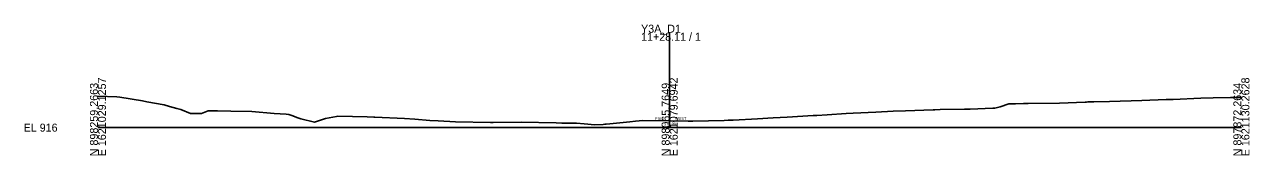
# Model space of a CAD drawing. Extents: x -12685 to 1621059, y -3463 to 898072.
# Drawn here: x -11285.4 to -10856.9, y -3463 to -3417.3 of the extents above; entities that cross this region are included whole.
import ezdxf

# ---------------------------------------------------------------- set-up
doc = ezdxf.new("R2010")
doc.units = 0
for name, color, linetype in [('Exist Cross Section Cell', 7, 'Continuous'), ('Exist XS Center Line Elevation Label', 7, 'Continuous'), ('Exist XS Ground Line', 7, 'Continuous'), ('Prop XS SE Text', 7, 'Continuous')]:
    doc.layers.add(name, color=color, linetype=linetype)

msp = doc.modelspace()

# ---------------------------------------------------------------- linework, layer by layer
at = {"layer": 'Exist Cross Section Cell'}
for p, q in [((-11059.76, -3453.26), (-11059.76, -3420.16)), ((-11259.75, -3453.26), (-11059.76, -3453.26)), ((-11059.76, -3453.26), (-10859.76, -3453.26))]:
    msp.add_line(p, q, dxfattribs=at)
at = {"layer": 'Exist XS Ground Line'}
msp.add_lwpolyline([(-11259.75, -3442.23), (-11253.19, -3442.54), (-11252.05, -3442.64), (-11244.22, -3443.91), (-11242.6, -3444.29), (-11236.58, -3445.35), (-11234.72, -3445.85), (-11232.14, -3446.57), (-11230.75, -3446.96), (-11227.4, -3448.36), (-11226.07, -3448.3), (-11223.5, -3448.36), (-11221.82, -3447.69), (-11221.25, -3447.42), (-11220.06, -3447.42), (-11217.9, -3447.39), (-11213.27, -3447.48), (-11205.9, -3447.64), (-11198.06, -3448.31), (-11196.05, -3448.45), (-11193.92, -3448.58), (-11192.94, -3448.65), (-11191.96, -3449.03), (-11189.88, -3449.86), (-11188.82, -3450.15), (-11184.03, -3451.3), (-11182.26, -3450.75), (-11180.2, -3450.11), (-11176.25, -3449.34), (-11175.89, -3449.29), (-11165.58, -3449.52), (-11163.26, -3449.58), (-11162.91, -3449.59), (-11152.56, -3450.08), (-11148.85, -3450.31), (-11143.71, -3450.73), (-11140.7, -3450.9), (-11134.71, -3451.2), (-11122.47, -3451.43), (-11122, -3451.43), (-11121.52, -3451.43), (-11111.66, -3451.3), (-11099.41, -3451.61), (-11097.53, -3451.67), (-11094.27, -3451.66), (-11092.29, -3451.68), (-11089.67, -3451.9), (-11085.97, -3452.25), (-11083.07, -3452.13), (-11082.42, -3452.09), (-11081.97, -3452.09), (-11080.68, -3451.98), (-11073.68, -3451.22), (-11071.67, -3451.02), (-11069.16, -3450.76), (-11059.76, -3450.87), (-11053.23, -3450.95), (-11051.63, -3450.96), (-11040.74, -3450.77), (-11039.31, -3450.71), (-11037.56, -3450.6), (-11028.97, -3450.15), (-11023.57, -3449.89), (-11018.64, -3449.61), (-11009.57, -3449.08), (-11008.3, -3449), (-11004.71, -3448.75), (-10997.96, -3448.31), (-10995.58, -3448.19), (-10987.63, -3447.88), (-10981.59, -3447.57), (-10977.29, -3447.37), (-10967.59, -3447.03), (-10966.95, -3447), (-10965.15, -3446.98), (-10956.62, -3446.86), (-10954.6, -3446.82), (-10946.65, -3446.44), (-10946.03, -3446.44), (-10944.16, -3445.95), (-10941.05, -3444.92), (-10938.75, -3444.98), (-10935.95, -3444.89), (-10934.38, -3444.85), (-10923.41, -3444.77), (-10914.43, -3444.37), (-10913.98, -3444.35), (-10913.46, -3444.31), (-10911.41, -3444.23), (-10905.94, -3444.1), (-10894.6, -3443.81), (-10886.05, -3443.49), (-10884.27, -3443.41), (-10883.63, -3443.39), (-10873.93, -3442.96), (-10869.64, -3442.88), (-10863.59, -3442.72), (-10859.76, -3442.71)], dxfattribs=at)

# ---------------------------------------------------------------- texts
at = {"layer": 'Exist Cross Section Cell'}
for s, p in [('Y3A_D1', (-11069.75, -3420.16)), ('11+28.11 / 1', (-11069.75, -3422.96)), ('EL 916', (-11285.75, -3454.66))]:
    msp.add_text(s, height=2.8, dxfattribs=at).set_placement(p)
for s, p in [('E 1621029.1257', (-11256.95, -3463.26)), ('E 1621079.6942', (-11056.95, -3463.26)), ('E 1621130.2628', (-10856.95, -3463.26)), ('N 898259.2663', (-11259.75, -3463.26)), ('N 898065.7649', (-11059.76, -3463.26)), ('N 897872.2634', (-10859.76, -3463.26))]:
    msp.add_text(s, height=2.8, rotation=90, dxfattribs=at).set_placement(p)
at = {"layer": 'Exist XS Center Line Elevation Label'}
msp.add_text('918.39', height=1, dxfattribs=at).set_placement((-11061.77, -3452.51))
at = {"layer": 'Prop XS SE Text'}
for rotation, p in [(1.1458, (-11064.87, -3450.68)), (358.8542, (-11057.9, -3450.53))]:
    msp.add_text('EXIST', height=1, rotation=rotation, dxfattribs=at).set_placement(p)

doc.saveas('drawing.dxf')
